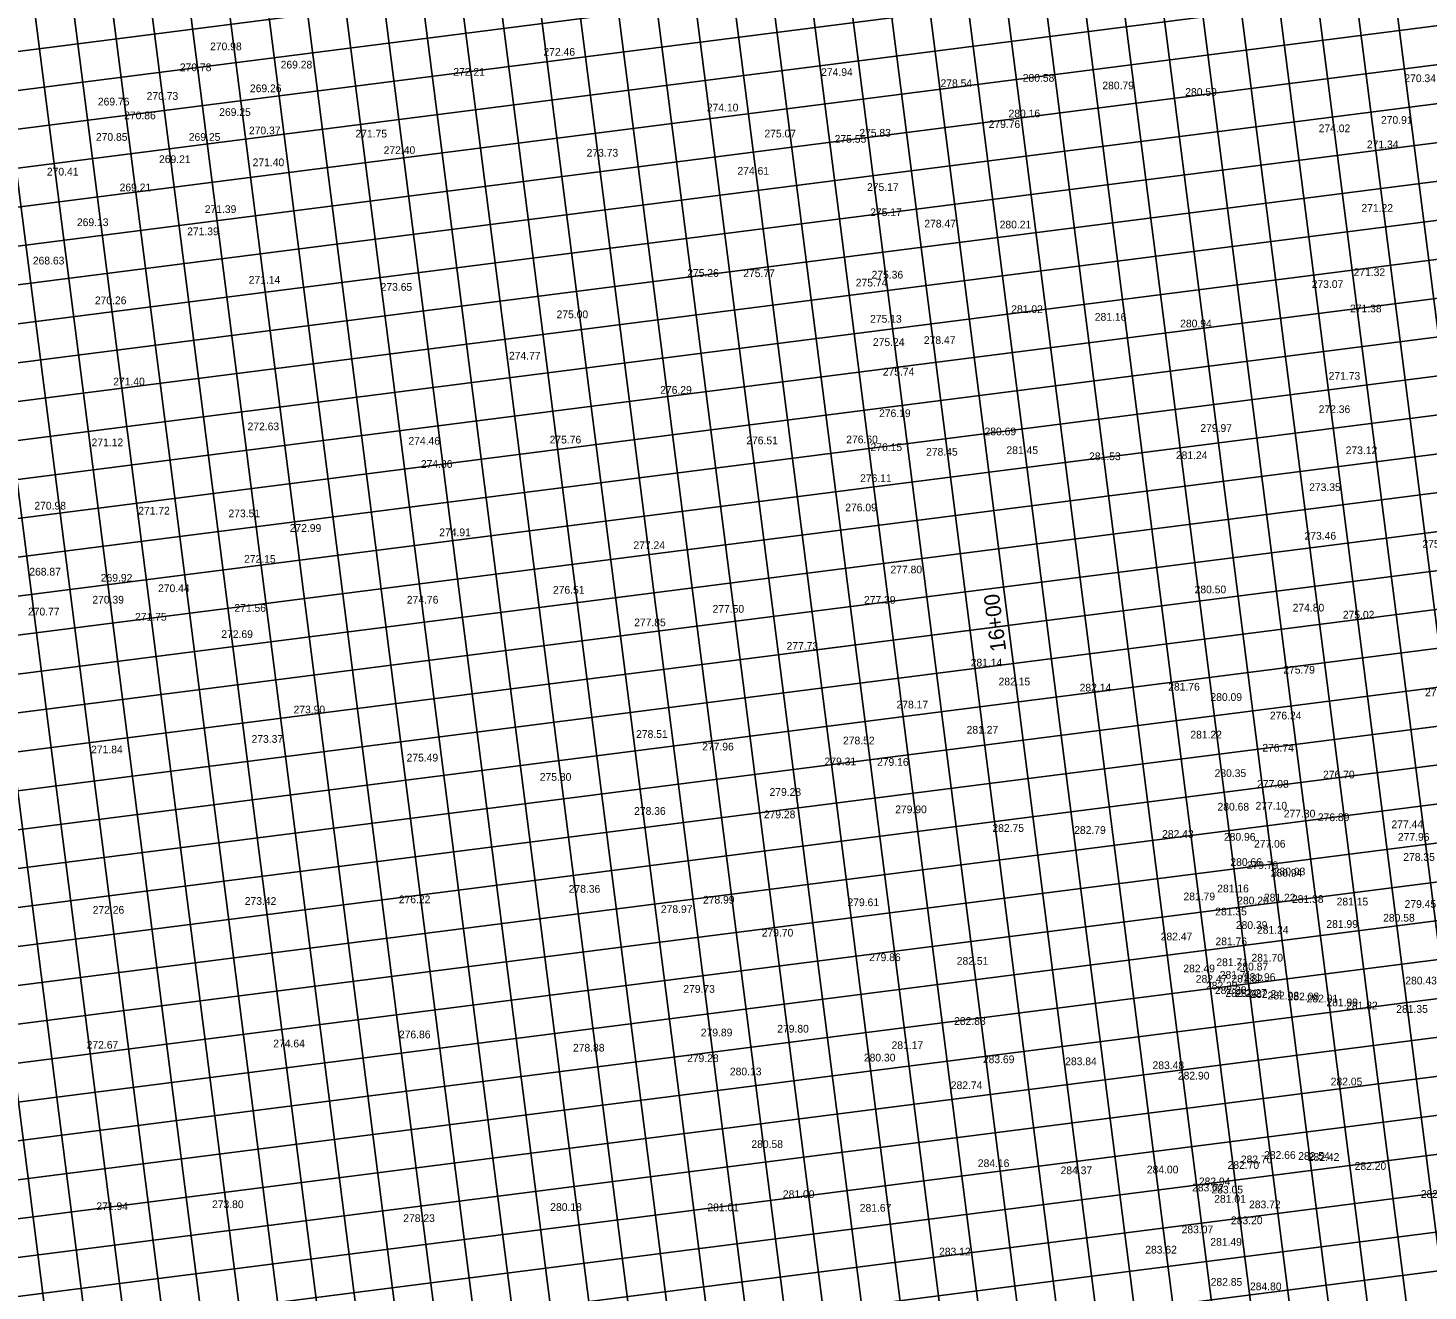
# Model space of a CAD drawing. Extents: x 2166991 to 2168450, y 842134 to 844444.
# Drawn here: x 2167951.5 to 2168132.8, y 843150.2 to 843313.8 of the extents above; entities that cross this region are included whole.
import ezdxf

# ---------------------------------------------------------------- set-up
doc = ezdxf.new("R2010")
doc.units = 0
for name, color, linetype in [('Exist Plan Preparation Drainage Notes Label', 7, 'Continuous'), ('Prop Drainage Structure Pipe Alternate 18in Label', 7, 'Continuous'), ('Scratch_Level_3', 7, 'Continuous')]:
    doc.layers.add(name, color=color, linetype=linetype)

msp = doc.modelspace()

# ---------------------------------------------------------------- linework, layer by layer
at = {"layer": 'Exist Plan Preparation Drainage Notes Label'}
for p, q in [((2168181.94, 842821.17), (2168023.56, 844061.1)), ((2168132.34, 842814.84), (2167973.96, 844054.76)), ((2168082.74, 842808.5), (2167924.37, 844048.43)), ((2168033.15, 842802.17), (2167874.77, 844042.09)), ((2168183.73, 842846.6), (2168031.69, 844036.93)), ((2168188.69, 842847.24), (2168036.65, 844037.57)), ((2168168.85, 842844.7), (2168016.81, 844035.03)), ((2168173.81, 842845.34), (2168021.77, 844035.67)), ((2168153.97, 842842.8), (2168001.93, 844033.13)), ((2168158.93, 842843.44), (2168006.89, 844033.77)), ((2168163.89, 842844.07), (2168011.85, 844034.4)), ((2168144.05, 842841.54), (2167992.01, 844031.86)), ((2168149.01, 842842.17), (2167996.97, 844032.5)), ((2168134.13, 842840.27), (2167982.09, 844030.6)), ((2168139.09, 842840.9), (2167987.05, 844031.23)), ((2168114.29, 842837.73), (2167962.25, 844028.06)), ((2168119.25, 842838.37), (2167967.21, 844028.7)), ((2168124.21, 842839), (2167972.17, 844029.33)), ((2168099.41, 842835.83), (2167947.37, 844026.16)), ((2168104.37, 842836.47), (2167952.33, 844026.8)), ((2168109.33, 842837.1), (2167957.29, 844027.43)), ((2168084.53, 842833.93), (2167932.49, 844024.26)), ((2168089.49, 842834.57), (2167937.45, 844024.9)), ((2168094.45, 842835.2), (2167942.41, 844025.53)), ((2168069.66, 842832.03), (2167917.61, 844022.36)), ((2168074.61, 842832.67), (2167922.57, 844023)), ((2168054.78, 842830.13), (2167902.74, 844020.46)), ((2168059.74, 842830.77), (2167907.69, 844021.1)), ((2168064.7, 842831.4), (2167912.65, 844021.73)), ((2168039.9, 842828.23), (2167887.86, 844018.56)), ((2168044.86, 842828.87), (2167892.82, 844019.19)), ((2168049.82, 842829.5), (2167897.78, 844019.83)), ((2168034.94, 842827.6), (2167882.9, 844017.93)), ((2168015.1, 842825.06), (2167863.06, 844015.39)), ((2168020.06, 842825.7), (2167868.02, 844016.03)), ((2168025.02, 842826.33), (2167872.98, 844016.66)), ((2168000.22, 842823.16), (2167848.18, 844013.49)), ((2168005.18, 842823.8), (2167853.14, 844014.13)), ((2168010.14, 842824.43), (2167858.1, 844014.76)), ((2167995.26, 842822.53), (2167843.22, 844012.86)), ((2168166.28, 843338.36), (2167670.31, 843275.01)), ((2168166.92, 843333.4), (2167670.95, 843270.05)), ((2168167.55, 843328.44), (2167671.58, 843265.09)), ((2168168.18, 843323.48), (2167672.21, 843260.13)), ((2168168.82, 843318.52), (2167672.85, 843255.17)), ((2168169.45, 843313.56), (2167673.48, 843250.21)), ((2168170.08, 843308.6), (2167674.11, 843245.25)), ((2168170.72, 843303.64), (2167674.75, 843240.29)), ((2168171.35, 843298.68), (2167650.58, 843232.16)), ((2168171.98, 843293.72), (2167676.01, 843230.37)), ((2168172.62, 843288.76), (2167676.65, 843225.41)), ((2168173.25, 843283.8), (2167677.28, 843220.45)), ((2168173.88, 843278.84), (2167677.91, 843215.49)), ((2168174.52, 843273.88), (2167678.55, 843210.53)), ((2168175.15, 843268.92), (2167679.18, 843205.57)), ((2168175.78, 843263.96), (2167679.81, 843200.61)), ((2168176.42, 843259), (2167680.45, 843195.65)), ((2168177.05, 843254.04), (2167681.08, 843190.69)), ((2168177.69, 843249.08), (2167656.92, 843182.56)), ((2168178.32, 843244.12), (2167682.35, 843180.77)), ((2168178.95, 843239.16), (2167682.98, 843175.81)), ((2168179.59, 843234.2), (2167683.62, 843170.85)), ((2168180.22, 843229.24), (2167684.25, 843165.89)), ((2168180.85, 843224.28), (2167684.88, 843160.93)), ((2168181.49, 843219.32), (2167685.52, 843155.97)), ((2168182.12, 843214.36), (2167686.15, 843151.01)), ((2168182.75, 843209.4), (2167686.78, 843146.05)), ((2168183.39, 843204.44), (2167687.42, 843141.09)), ((2168184.02, 843199.48), (2167663.25, 843132.97)), ((2168184.65, 843194.53), (2167688.68, 843131.17)), ((2168185.29, 843189.57), (2167689.32, 843126.21)), ((2168185.92, 843184.61), (2167689.95, 843121.26)), ((2168186.55, 843179.65), (2167690.58, 843116.3)), ((2168187.19, 843174.69), (2167691.22, 843111.34)), ((2168187.82, 843169.73), (2167691.85, 843106.38)), ((2168188.45, 843164.77), (2167692.48, 843101.42)), ((2168189.09, 843159.81), (2167693.12, 843096.46))]:
    msp.add_line(p, q, dxfattribs=at)
at = {"layer": 'Prop Drainage Structure Pipe Alternate 18in Label'}
msp.add_line((2168078.49, 843236.4), (2168050.94, 843232.88), dxfattribs=at)

# ---------------------------------------------------------------- texts
msp.add_text('16+00', height=2, rotation=97.279, dxfattribs=at).set_placement((2168078.22, 843233.14))
at = {"layer": 'Scratch_Level_3'}
for s, p in [('270.98', (2167975.1, 843310.91)), ('269.28', (2167984.24, 843308.55)), ('272.46', (2168018.28, 843310.2)), ('270.78', (2167971.18, 843308.2)), ('272.21', (2168006.6, 843307.61)), ('274.94', (2168054.25, 843307.58)), ('280.58', (2168080.36, 843306.83)), ('270.34', (2168129.79, 843306.78)), ('269.26', (2167980.26, 843305.48)), ('278.54', (2168069.71, 843306.14)), ('280.79', (2168090.67, 843305.85)), ('280.59', (2168101.41, 843305)), ('269.76', (2167960.56, 843303.76)), ('270.73', (2167966.88, 843304.49)), ('270.86', (2167963.97, 843301.97)), ('269.25', (2167976.28, 843302.4)), ('274.10', (2168039.44, 843302.99)), ('280.16', (2168078.52, 843302.22)), ('270.91', (2168126.76, 843301.38)), ('270.37', (2167980.13, 843300.02)), ('271.75', (2167993.93, 843299.61)), ('275.07', (2168046.9, 843299.62)), ('275.83', (2168059.19, 843299.72)), ('279.76', (2168075.94, 843300.84)), ('274.02', (2168118.69, 843300.3)), ('270.85', (2167960.31, 843299.18)), ('269.25', (2167972.34, 843299.18)), ('275.55', (2168056, 843298.93)), ('271.34', (2168124.94, 843298.22)), ('269.21', (2167968.48, 843296.3)), ('271.40', (2167980.61, 843295.89)), ('272.40', (2167997.58, 843297.47)), ('273.73', (2168023.87, 843297.13)), ('270.41', (2167953.96, 843294.68)), ('274.61', (2168043.41, 843294.79)), ('269.21', (2167963.38, 843292.64)), ('275.17', (2168060.19, 843292.69)), ('271.39', (2167974.41, 843289.83)), ('275.17', (2168060.6, 843289.43)), ('271.22', (2168124.23, 843289.98)), ('269.13', (2167957.85, 843288.13)), ('271.39', (2167972.13, 843286.95)), ('278.47', (2168067.61, 843287.95)), ('280.21', (2168077.37, 843287.83)), ('268.63', (2167952.14, 843283.16)), ('275.26', (2168036.9, 843281.56)), ('275.77', (2168044.16, 843281.52)), ('275.36', (2168060.78, 843281.34)), ('271.32', (2168123.21, 843281.66)), ('271.14', (2167980.1, 843280.67)), ('273.65', (2167997.19, 843279.75)), ('275.74', (2168058.73, 843280.31)), ('273.07', (2168117.79, 843280.12)), ('270.26', (2167960.17, 843278.01)), ('275.00', (2168019.98, 843276.2)), ('281.02', (2168078.87, 843276.87)), ('271.38', (2168122.75, 843276.96)), ('275.13', (2168060.59, 843275.62)), ('281.16', (2168089.69, 843275.87)), ('280.94', (2168100.75, 843275.01)), ('275.24', (2168060.95, 843272.6)), ('278.47', (2168067.55, 843272.86)), ('274.77', (2168013.81, 843270.84)), ('275.74', (2168062.23, 843268.77)), ('271.40', (2167962.55, 843267.49)), ('271.73', (2168119.98, 843268.23)), ('276.29', (2168033.4, 843266.41)), ('276.19', (2168061.75, 843263.39)), ('272.36', (2168118.69, 843263.91)), ('272.63', (2167979.95, 843261.68)), ('279.97', (2168103.37, 843261.47)), ('271.12', (2167959.75, 843259.61)), ('274.46', (2168000.79, 843259.81)), ('275.76', (2168019.08, 843259.97)), ('276.51', (2168044.55, 843259.86)), ('276.60', (2168057.5, 843259.99)), ('280.69', (2168075.41, 843261.03)), ('276.15', (2168060.64, 843258.99)), ('278.45', (2168067.84, 843258.39)), ('281.45', (2168078.25, 843258.6)), ('281.53', (2168088.95, 843257.81)), ('281.24', (2168100.19, 843257.94)), ('273.12', (2168122.19, 843258.59)), ('274.86', (2168002.4, 843256.81)), ('276.11', (2168059.29, 843254.97)), ('273.35', (2168117.46, 843253.81)), ('270.98', (2167952.34, 843251.41)), ('271.72', (2167965.79, 843250.76)), ('276.09', (2168057.37, 843251.18)), ('273.51', (2167977.48, 843250.41)), ('272.99', (2167985.41, 843248.52)), ('274.91', (2168004.78, 843247.96)), ('273.46', (2168116.86, 843247.51)), ('277.24', (2168029.93, 843246.29)), ('275.37', (2168132.13, 843246.47)), ('272.15', (2167979.5, 843244.52)), ('268.87', (2167951.68, 843242.86)), ('269.92', (2167960.94, 843242.07)), ('277.80', (2168063.23, 843243.14)), ('270.44', (2167968.36, 843240.71)), ('276.51', (2168019.51, 843240.51)), ('280.50', (2168102.62, 843240.56)), ('270.39', (2167959.85, 843239.23)), ('271.56', (2167978.25, 843238.16)), ('274.76', (2168000.58, 843239.23)), ('277.50', (2168040.18, 843238.04)), ('277.39', (2168059.8, 843239.21)), ('274.80', (2168115.32, 843238.2)), ('270.77', (2167951.51, 843237.69)), ('271.75', (2167965.38, 843237.01)), ('277.85', (2168030.03, 843236.29)), ('275.02', (2168121.82, 843237.29)), ('272.69', (2167976.55, 843234.77)), ('277.73', (2168049.77, 843233.25)), ('281.14', (2168073.62, 843231.08)), ('275.79', (2168114.11, 843230.16)), ('282.15', (2168077.23, 843228.63)), ('282.14', (2168087.73, 843227.84)), ('281.76', (2168099.2, 843227.96)), ('276.96', (2168132.47, 843227.22)), ('278.17', (2168064.01, 843225.65)), ('280.09', (2168104.67, 843226.62)), ('273.90', (2167985.91, 843225)), ('276.24', (2168112.37, 843224.22)), ('278.51', (2168030.28, 843221.83)), ('281.27', (2168073.09, 843222.38)), ('281.22', (2168102.07, 843221.75)), ('271.84', (2167959.69, 843219.83)), ('273.37', (2167980.47, 843221.19)), ('277.96', (2168038.84, 843220.2)), ('278.52', (2168057.08, 843220.99)), ('276.74', (2168111.39, 843220.05)), ('275.49', (2168000.55, 843218.77)), ('279.31', (2168054.69, 843218.28)), ('279.16', (2168061.49, 843218.21)), ('275.80', (2168017.8, 843216.27)), ('280.35', (2168105.21, 843216.76)), ('276.70', (2168119.26, 843216.58)), ('279.28', (2168047.56, 843214.32)), ('277.08', (2168110.72, 843215.37)), ('280.68', (2168105.59, 843212.41)), ('277.10', (2168110.51, 843212.54)), ('278.36', (2168030.02, 843211.86)), ('279.28', (2168046.82, 843211.42)), ('279.90', (2168063.84, 843212.07)), ('277.30', (2168114.17, 843211.52)), ('276.89', (2168118.58, 843211.05)), ('282.75', (2168076.43, 843209.65)), ('282.79', (2168087.02, 843209.39)), ('282.43', (2168098.41, 843208.88)), ('277.44', (2168128.12, 843210.13)), ('280.96', (2168106.42, 843208.51)), ('277.06', (2168110.31, 843207.61)), ('277.96', (2168128.95, 843208.5)), ('280.66', (2168107.25, 843205.24)), ('278.35', (2168129.65, 843205.9)), ('279.79', (2168109.37, 843204.83)), ('280.94', (2168112.48, 843203.85)), ('280.93', (2168112.87, 843204.02)), ('278.36', (2168021.55, 843201.77)), ('281.16', (2168105.55, 843201.82)), ('273.42', (2167979.59, 843200.2)), ('276.22', (2167999.54, 843200.41)), ('278.99', (2168038.94, 843200.36)), ('279.61', (2168057.66, 843200.03)), ('281.79', (2168101.18, 843200.79)), ('280.20', (2168108.14, 843200.26)), ('281.22', (2168111.6, 843200.64)), ('281.38', (2168115.23, 843200.45)), ('281.15', (2168121.02, 843200.12)), ('279.45', (2168129.82, 843199.81)), ('272.26', (2167959.89, 843199.05)), ('278.97', (2168033.49, 843199.14)), ('281.35', (2168105.29, 843198.84)), ('280.58', (2168127.04, 843198.03)), ('279.70', (2168046.55, 843196.09)), ('280.39', (2168107.96, 843197.08)), ('281.24', (2168110.7, 843196.46)), ('281.99', (2168119.69, 843197.22)), ('282.47', (2168098.23, 843195.6)), ('281.76', (2168105.32, 843194.97)), ('279.86', (2168060.46, 843192.91)), ('281.70', (2168109.98, 843192.85)), ('282.51', (2168071.81, 843192.44)), ('282.49', (2168101.16, 843191.46)), ('281.71', (2168105.44, 843192.26)), ('280.87', (2168108.06, 843191.7)), ('282.47', (2168102.77, 843190.11)), ('282.29', (2168104.09, 843189.24)), ('281.71', (2168105.88, 843190.63)), ('281.82', (2168107.38, 843190.13)), ('281.96', (2168109, 843190.34)), ('280.43', (2168129.91, 843189.89)), ('279.73', (2168036.39, 843188.81)), ('282.29', (2168105.25, 843188.65)), ('282.24', (2168106.6, 843188.27)), ('282.27', (2168107.89, 843188.28)), ('282.24', (2168109.85, 843188.15)), ('282.08', (2168112.07, 843187.94)), ('282.08', (2168114.66, 843187.83)), ('282.01', (2168117.13, 843187.56)), ('281.99', (2168119.69, 843187.06)), ('281.82', (2168122.24, 843186.66)), ('281.35', (2168128.74, 843186.21)), ('279.80', (2168048.56, 843183.65)), ('282.83', (2168071.47, 843184.65)), ('274.64', (2167983.28, 843181.74)), ('276.86', (2167999.56, 843182.91)), ('279.89', (2168038.66, 843183.16)), ('272.67', (2167959.11, 843181.57)), ('278.88', (2168022.1, 843181.19)), ('279.28', (2168036.88, 843179.83)), ('280.30', (2168059.78, 843179.91)), ('281.17', (2168063.37, 843181.52)), ('280.13', (2168042.43, 843178.11)), ('283.69', (2168075.19, 843179.69)), ('283.84', (2168085.86, 843179.43)), ('283.48', (2168097.17, 843178.92)), ('282.74', (2168071.04, 843176.33)), ('282.90', (2168100.45, 843177.57)), ('282.05', (2168120.25, 843176.81)), ('280.58', (2168045.21, 843168.7)), ('282.66', (2168111.62, 843167.29)), ('282.54', (2168116.04, 843167.16)), ('284.16', (2168074.54, 843166.23)), ('284.37', (2168085.26, 843165.31)), ('284.00', (2168096.43, 843165.41)), ('282.70', (2168106.89, 843166)), ('282.70', (2168108.61, 843166.72)), ('282.42', (2168117.28, 843167.03)), ('282.20', (2168123.35, 843165.87)), ('282.94', (2168103.17, 843163.87)), ('281.00', (2168049.29, 843162.22)), ('283.02', (2168102.29, 843163.08)), ('283.05', (2168104.8, 843162.81)), ('282.20', (2168131.92, 843162.24)), ('271.94', (2167960.37, 843160.66)), ('273.80', (2167975.35, 843160.91)), ('280.18', (2168019.16, 843160.55)), ('281.01', (2168039.51, 843160.51)), ('281.67', (2168059.25, 843160.45)), ('281.01', (2168105.16, 843161.61)), ('283.72', (2168109.67, 843160.89)), ('278.23', (2168000.12, 843159.11)), ('283.20', (2168107.33, 843158.83)), ('283.07', (2168100.94, 843157.65)), ('283.12', (2168069.52, 843154.78)), ('283.62', (2168096.23, 843155.03)), ('281.49', (2168104.66, 843156.04)), ('282.85', (2168104.7, 843150.85)), ('284.80', (2168109.79, 843150.27))]:
    msp.add_text(s, height=1, dxfattribs=at).set_placement(p)

doc.saveas('drawing.dxf')
